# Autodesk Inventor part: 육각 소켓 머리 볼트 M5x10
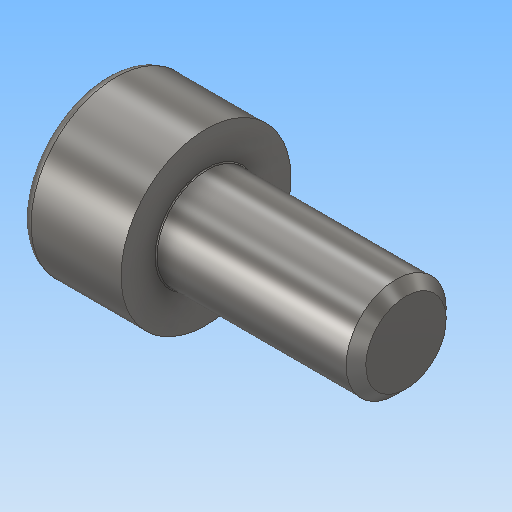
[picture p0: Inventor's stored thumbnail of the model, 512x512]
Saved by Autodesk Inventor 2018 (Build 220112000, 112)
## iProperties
Created: 2024-09
Part Number: 육각 소켓 머리 볼트 M5x10
Material: 강철, 연강
Description: 6각머리 태핑 나사
Document SubType Name: Modeling
Designer: home
Density: 7.85 g/cm^3
Appearance: 기본값
Author: jhkim
Sending System: Autodesk Inventor 2025
Preprocessor: ST-DEVELOPER v20
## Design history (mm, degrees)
feature "Solid1"
node "솔리드1"
